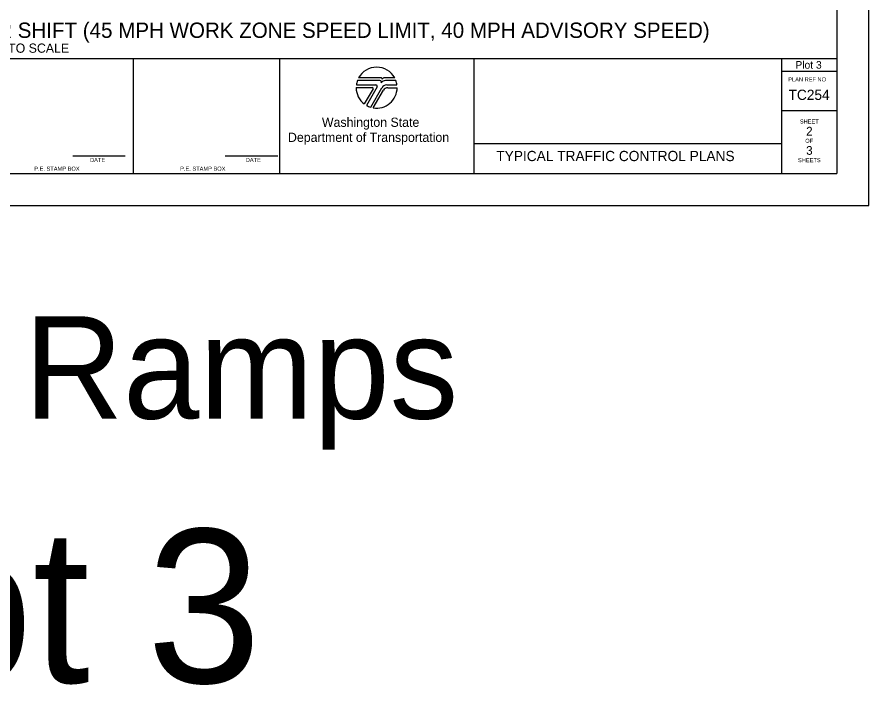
# Model space of a CAD drawing. Extents: x 99999 to 100116, y 99995 to 100013.
# Drawn here: x 100047.75 to 100056.06, y 99995.01 to 100001.53 of the extents above; entities that cross this region are included whole.
import ezdxf

# ---------------------------------------------------------------- set-up
doc = ezdxf.new("R2010")
doc.units = 0
for name, color, linetype in [('SH_DE_DetailHeading1Text', 7, 'Continuous'), ('SH_GI_PlotLimits', 7, 'Continuous'), ('SH_GI_SheetBorder', 7, 'Continuous'), ('SH_GI_SheetLocationText', 7, 'Continuous'), ('SH_GI_SheetTextInCells', 7, 'Continuous'), ('SH_GI_TitleBlockText', 7, 'Continuous'), ('SH_GI_WSDOTLogo', 7, 'Continuous')]:
    doc.layers.add(name, color=color, linetype=linetype)

msp = doc.modelspace()

# ---------------------------------------------------------------- linework, layer by layer
at = {"layer": 'SH_GI_PlotLimits'}
msp.add_lwpolyline([(100039.0625, 99999.6875), (100056.0625, 99999.6875), (100056.0625, 100010.6875), (100039.0625, 100010.6875)], close=True, dxfattribs=at)
at = {"layer": 'SH_GI_SheetBorder'}
for p, q in [((100055.75, 100010.375), (100055.75, 100000)), ((100040, 100001.1259), (100055.75, 100001.1259)), ((100048.8828, 100000), (100048.8828, 100001.1259)), ((100050.3089, 100001.1259), (100050.3089, 100000)), ((100052.2055, 100001.1259), (100052.2055, 100000)), ((100055.2079, 100001.1259), (100055.2079, 100000)), ((100055.2079, 100001.0008), (100055.75, 100001.0008)), ((100055.2079, 100000.6176), (100055.75, 100000.6176)), ((100052.2055, 100000.2955), (100055.2079, 100000.2955)), ((100048.2903, 100000.1733), (100048.802, 100000.1733)), ((100049.7797, 100000.1733), (100050.2914, 100000.1733)), ((100040, 100000), (100055.75, 100000))]:
    msp.add_line(p, q, dxfattribs=at)
at = {"layer": 'SH_GI_WSDOTLogo'}
for p, q in [((100051.2894, 100000.9094), (100051.0697, 100000.9094)), ((100051.303, 100000.9354), (100051.0815, 100000.9354)), ((100051.433, 100000.9354), (100051.3351, 100000.9354)), ((100051.343, 100000.9094), (100051.3429, 100000.9094)), ((100051.4448, 100000.9094), (100051.343, 100000.9094)), ((100051.0572, 100000.84), (100051.2148, 100000.84)), ((100051.059, 100000.8661), (100051.2496, 100000.8661)), ((100051.222, 100000.8277), (100051.1364, 100000.6807)), ((100051.261, 100000.8464), (100051.1567, 100000.6672)), ((100051.1989, 100000.6487), (100051.3089, 100000.839)), ((100051.2244, 100000.6428), (100051.3242, 100000.8156)), ((100051.3558, 100000.8661), (100051.4555, 100000.8661)), ((100051.3655, 100000.8394), (100051.4572, 100000.8394))]:
    msp.add_line(p, q, dxfattribs=at)
for centre, radius, start, end in [((100051.2572, 100000.84), 0.2, 28.47865, 151.53204), ((100051.2572, 100000.84), 0.2, 159.69598, 172.50569), ((100051.2894, 100000.8946), 0.0148, 327.8418, 89.99855), ((100051.3429, 100000.861), 0.0484, 89.99529, 147.82376), ((100051.303, 100000.9263), 0.00903, 329.87418, 90.00328), ((100051.3352, 100000.9066), 0.0287, 90.00721, 148.16763), ((100051.2572, 100000.84), 0.2, 7.49431, 20.29406), ((100051.2572, 100000.84), 0.2, 179.99864, 232.84327), ((100051.2149, 100000.8318), 0.0082, 329.74356, 90), ((100051.2572, 100000.84), 0.2, 260.54554, 359.80857), ((100051.2497, 100000.853), 0.0131, 329.76834, 90), ((100051.3558, 100000.8119), 0.0542, 90, 149.99738), ((100051.3654, 100000.7918), 0.0476, 90, 150.05432), ((100051.2572, 100000.84), 0.2, 239.79292, 253.0448)]:
    msp.add_arc(centre, radius, start, end, dxfattribs=at)

# ---------------------------------------------------------------- texts
at = {"layer": 'SH_DE_DetailHeading1Text'}
for s, height, p in [("FREEWAY (2 LANES): SINGLE LEFT LANE CLOSURE, 9' MAX RIGHT SHOULDER SHIFT (45 MPH WORK ZONE SPEED LIMIT, 40 MPH ADVISORY SPEED)", 0.15, (100040.0913, 100001.3259)), ('NOT TO SCALE', 0.09, (100047.3727, 100001.1809))]:
    msp.add_text(s, height=height, rotation=360, dxfattribs=at).set_placement(p)
at = {"layer": 'SH_GI_SheetBorder'}
msp.add_text('PLAN REF NO', height=0.040032, dxfattribs=at).set_placement((100055.2747, 100000.9008))
at = {"layer": 'SH_GI_SheetLocationText'}
for s, height, p in [('Plot 3', 0.075, (100055.3446, 100001.025)), ('Right Ramps', 1, (100044.324, 99997.6071)), ('Plot 3', 1.5, (100045.0008, 99995.0267))]:
    msp.add_text(s, height=height, dxfattribs=at).set_placement(p)
at = {"layer": 'SH_GI_SheetTextInCells'}
for s, height, p in [('Washington State', 0.090072, (100050.7229, 100000.4571)), ('SHEET', 0.04003, (100055.3877, 100000.4896)), ('Department of Transportation', 0.090072, (100050.3916, 100000.3101)), ('OF', 0.04003, (100055.4406, 100000.3008)), ('DATE', 0.04003, (100048.4597, 100000.1141)), ('DATE', 0.04003, (100049.9794, 100000.1141)), ('SHEETS', 0.04003, (100055.3698, 100000.112)), ('P.E. STAMP BOX', 0.040032, (100047.915, 100000.0286)), ('P.E. STAMP BOX', 0.040032, (100049.339, 100000.0286))]:
    msp.add_text(s, height=height, dxfattribs=at).set_placement(p)
at = {"layer": 'SH_GI_TitleBlockText'}
for s, height, p in [('TC254', 0.1, (100055.2776, 100000.72)), ('2', 0.085, (100055.4493, 100000.3723)), ('3', 0.085, (100055.4493, 100000.1843)), ('TYPICAL TRAFFIC CONTROL PLANS', 0.1, (100052.4251, 100000.1224))]:
    msp.add_text(s, height=height, dxfattribs=at).set_placement(p)

doc.saveas('drawing.dxf')
